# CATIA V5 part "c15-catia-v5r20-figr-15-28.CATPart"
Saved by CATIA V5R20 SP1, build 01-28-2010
Part number: Part1
Bounding box of the stored display mesh (mm): x -61.282 to 61.282, y -26.72 to 26.72, z 0 to 45.75
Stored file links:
  D:\v5_r20\psrt_files_downloaded\c15\c15-catia-v5r20-figr-15-28.CATPart
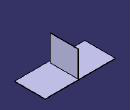
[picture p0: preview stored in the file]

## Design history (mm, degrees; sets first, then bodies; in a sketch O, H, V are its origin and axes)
SheetMetalParameters1: Thickness 0.75, BendRadius 1, KFactor 0.356492 {= log(min(100,max(20*SheetMetalParameters1.BendRadius,SheetMetalParameters1.Thickness)/SheetMetalParameters1.Thickness))/log(100)/2}, ReliefRadialLength 1, ReliefAxialLength 2, MinimumBendRadius 0
Body1 (main body)
  Sketch1 on xy-plane, origin (0, 0, 0), H (1, 0, 0), V (0, 1, 0)
    line L1 (61.282, 26.7197) -> (61.282, -26.7197)
    line L2 (61.282, -26.7197) -> (-61.282, -26.7197)
    line L3 (-61.282, -26.7197) -> (-61.282, 26.7197)
    line L4 (-61.282, 26.7197) -> (61.282, 26.7197)
    vertical: L1 V, L3 V
    horizontal: L2 H, L4 H
    equidistance: L1 L3 O, L2 L4 O
  Wall1: Thickness 0.75, Profile Sketch1
  Sketch2 on face of Wall1, origin (0, 0, 0.75), H (1, 0, 0), V (0, 1, 0)
    line L1 (1.9015, 25.4615) -> (1.9015, -22.9675)
    vertical: L1 V
  d_Extrude1: Extrude_Thickness 0.75, Extrude_Profile Sketch2, Extrude_StartLength 45, Extrude_EndLength 0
